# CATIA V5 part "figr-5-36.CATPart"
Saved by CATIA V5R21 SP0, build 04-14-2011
Part number: Part1
Bounding box of the stored display mesh (mm): x -80 to 80, y -60 to 60, z 0 to 120
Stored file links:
  D:\CATIA V5R21 E-RESOURCES\CATIA-V5R21\catia-v5r21-prt\c05-catia-v5r20-prt\catia-v5r21-figr-5-36.CATPart
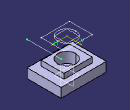
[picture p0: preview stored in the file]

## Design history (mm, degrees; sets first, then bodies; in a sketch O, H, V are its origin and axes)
Set1
  Plane1: type Offset, RefPlane xy-plane, Offset 120
Body1 (main body)
  Sketch1 on xy-plane, origin (0, 0, 0), H (1, 0, 0), V (0, 1, 0)
    line L1 (80, 60) -> (80, -60)
    line L2 (80, -60) -> (-80, -60)
    line L3 (-80, -60) -> (-80, 60)
    line L4 (-80, 60) -> (80, 60)
    circle A1 centre (0, 0) radius 31.6228
    line L5 (50, 40) -> (50, -40)
    line L6 (50, -40) -> (-50, -40)
    line L7 (-50, -40) -> (-50, 40)
    line L8 (-50, 40) -> (50, 40)
    vertical: L1 V, L3 V, L5 V, L7 V
    horizontal: L2 H, L4 H, L6 H, L8 H
    equidistance: L1 L3 O, L2 L4 O, L5 L7 O, L6 L8 O
  MultiPad1: profile Sketch1, domains (length 51; length 33; length 14)
  Sketch2 on Plane1, origin (0, 0, 120), H (1, 0, 0), V (0, 1, 0)
    projected line E1 (50, 40) -> (-50, 40) from edge [face of MultiPad1 | face of MultiPad1]
    projected line E2 (-50, 40) -> (-50, -40) from edge [face of MultiPad1 | face of MultiPad1]
    projected line E3 (-50, -40) -> (50, -40) from edge [face of MultiPad1 | face of MultiPad1]
    projected line E4 (50, -40) -> (50, 40) from edge [face of MultiPad1 | face of MultiPad1]
    projected circle E5 centre (0, 0) radius 31.6228 from edge [face of MultiPad1 | face of MultiPad1]
    projected line E6 (80, -60) -> (80, 60) from edge [face of MultiPad1 | face of MultiPad1]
